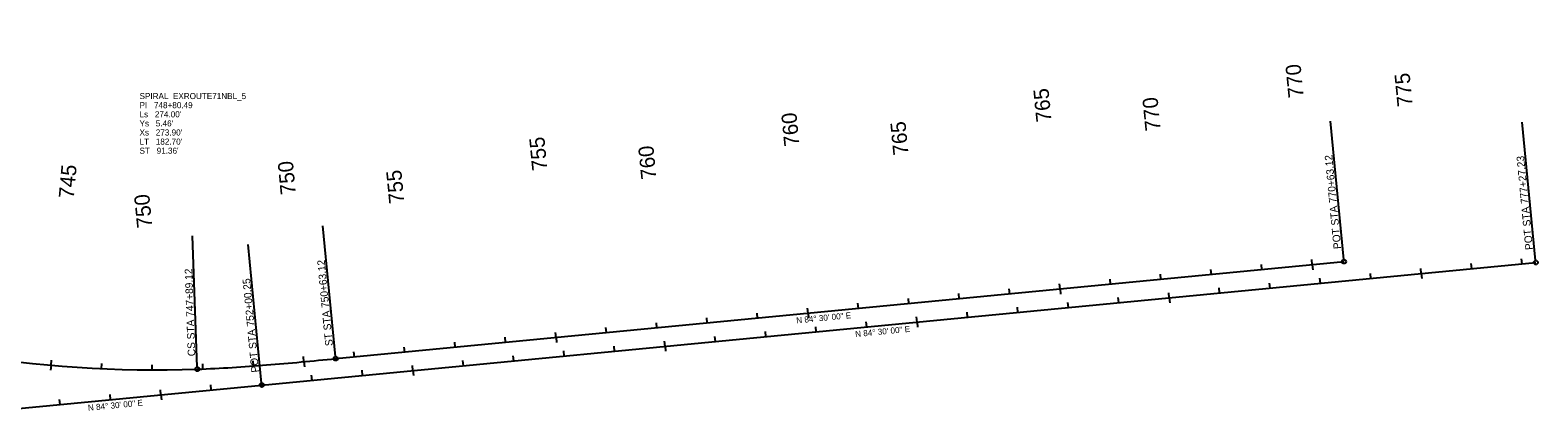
# Model space of a CAD drawing. Extents: x 2819977 to 2827606, y 116785 to 150320.
# Drawn here: x 2824629 to 2827606, y 145341 to 146093 of the extents above; entities that cross this region are included whole.
import ezdxf

# ---------------------------------------------------------------- set-up
doc = ezdxf.new("R2010")
doc.units = 0
for name, color, linetype in [('Default', 7, 'Continuous'), ('Modeling-Contours-Major-Existing', 7, 'Continuous'), ('Modeling-Contours-Minor-Existing', 7, 'Continuous'), ('Modeling-Triangle Verticies-Existing', 7, 'Continuous')]:
    doc.layers.add(name, color=color, linetype=linetype)

msp = doc.modelspace()

# ---------------------------------------------------------------- linework, layer by layer
at = {"layer": 'Default'}
msp.add_line((2825086.6, 145391.7), (2827601.9, 145633.9), dxfattribs=at)
msp.add_arc((2824876.4, 147713.4), 2291.8, 224.9911, 272.075, dxfattribs=at)
msp.add_open_spline([(2824959.3, 145423.1), (2824982.2, 145423.9), (2825027.8, 145426.2), (2825096.1, 145431.3), (2825164.3, 145437.2), (2825209.8, 145441.7), (2825232.5, 145443.9)], degree=3, dxfattribs=at)
at = {"layer": 'Modeling-Contours-Major-Existing'}
for p, q in [((2825086.6, 145391.7), (2827601.9, 145633.9)), ((2825232.5, 145443.9), (2827223.3, 145635.6)), ((2827060.9, 145619.9), (2827060, 145629.9)), ((2827160.5, 145629.5), (2827159.5, 145639.5)), ((2827160.5, 145629.5), (2827161.4, 145619.6)), ((2827475.3, 145621.7), (2827474.3, 145631.6)), ((2827574.8, 145631.2), (2827573.9, 145641.2)), ((2826762.3, 145591.2), (2826761.3, 145601.1)), ((2826861.8, 145600.8), (2826860.9, 145610.7)), ((2826961.4, 145610.3), (2826960.4, 145620.3)), ((2827176.7, 145592.9), (2827175.7, 145602.9)), ((2827276.2, 145602.5), (2827275.3, 145612.4)), ((2827375.8, 145612.1), (2827374.8, 145622)), ((2827375.8, 145612.1), (2827376.7, 145602.1)), ((2826463.7, 145562.4), (2826462.7, 145572.4)), ((2826563.2, 145572), (2826562.3, 145582)), ((2826662.8, 145581.6), (2826661.8, 145591.5)), ((2826662.8, 145581.6), (2826663.7, 145571.6)), ((2826878.1, 145564.1), (2826877.1, 145574.1)), ((2826977.6, 145573.7), (2826976.6, 145583.7)), ((2827077.1, 145583.3), (2827076.2, 145593.3)), ((2826165.1, 145533.7), (2826164.1, 145543.6)), ((2826264.6, 145543.3), (2826263.6, 145553.2)), ((2826364.1, 145552.8), (2826363.2, 145562.8)), ((2826579.4, 145535.4), (2826578.5, 145545.4)), ((2826679, 145545), (2826678, 145554.9)), ((2826778.5, 145554.6), (2826777.6, 145564.5)), ((2826878.1, 145564.1), (2826879, 145554.2)), ((2825866.4, 145504.9), (2825865.5, 145514.9)), ((2825966, 145514.5), (2825965, 145524.5)), ((2826065.5, 145524.1), (2826064.6, 145534)), ((2826165.1, 145533.7), (2826166, 145523.7)), ((2826181.3, 145497.1), (2826180.3, 145507)), ((2826280.8, 145506.6), (2826279.9, 145516.6)), ((2826380.4, 145516.2), (2826379.4, 145526.2)), ((2826380.4, 145516.2), (2826381.3, 145506.3)), ((2826479.9, 145525.8), (2826478.9, 145535.8)), ((2825567.8, 145476.2), (2825566.9, 145486.1)), ((2825667.4, 145485.7), (2825666.4, 145495.7)), ((2825667.4, 145485.7), (2825668.3, 145475.8)), ((2825766.9, 145495.3), (2825765.9, 145505.3)), ((2825882.7, 145468.3), (2825881.7, 145478.3)), ((2825982.2, 145477.9), (2825981.2, 145487.8)), ((2826081.7, 145487.5), (2826080.8, 145497.4)), ((2825169.7, 145437.9), (2825168.7, 145447.9)), ((2825269.2, 145447.4), (2825268.2, 145457.4)), ((2825368.7, 145457), (2825367.8, 145466.9)), ((2825468.3, 145466.6), (2825467.3, 145476.5)), ((2825584, 145439.6), (2825583.1, 145449.5)), ((2825683.6, 145449.1), (2825682.6, 145459.1)), ((2825783.1, 145458.7), (2825782.2, 145468.7)), ((2825882.7, 145468.3), (2825883.6, 145458.4)), ((2824670.5, 145430.8), (2824669.6, 145420.9)), ((2824670.5, 145430.8), (2824671.4, 145440.8)), ((2824770.3, 145424), (2824770.7, 145434)), ((2824870.2, 145421.6), (2824870.3, 145431.6)), ((2824970.2, 145423.5), (2824969.8, 145433.5)), ((2825070, 145429.4), (2825069.3, 145439.4)), ((2825169.7, 145437.9), (2825170.6, 145427.9)), ((2825285.4, 145410.8), (2825284.5, 145420.8)), ((2825385, 145420.4), (2825384, 145430.3)), ((2825385, 145420.4), (2825385.9, 145410.4)), ((2825484.5, 145430), (2825483.5, 145439.9)), ((2824572.2, 145342.1), (2825086.6, 145391.7)), ((2824986.8, 145382), (2824985.8, 145392)), ((2825086.3, 145391.6), (2825085.4, 145401.6)), ((2825185.9, 145401.2), (2825184.9, 145411.2)), ((2824688.2, 145353.3), (2824687.2, 145363.2)), ((2824787.7, 145362.9), (2824786.8, 145372.8)), ((2824887.3, 145372.5), (2824886.3, 145382.4)), ((2824887.3, 145372.5), (2824888.2, 145362.5))]:
    msp.add_line(p, q, dxfattribs=at)
msp.add_arc((2824876.4, 147713.4), 2291.8, 224.9911, 272.075, dxfattribs=at)
msp.add_open_spline([(2824959.3, 145423.1), (2824982.2, 145423.9), (2825027.8, 145426.2), (2825096.1, 145431.3), (2825164.3, 145437.2), (2825209.8, 145441.7), (2825232.5, 145443.9)], degree=3, dxfattribs=at)
at = {"layer": 'Modeling-Contours-Minor-Existing'}
for p, q in [((2827222.9, 145639.6), (2827196.6, 145913)), ((2827601.6, 145637.8), (2827575.2, 145911.3)), ((2824959.2, 145427.1), (2824949.8, 145686.6)), ((2825232.1, 145447.9), (2825207.2, 145706.4)), ((2825086.2, 145395.6), (2825059.9, 145669.2))]:
    msp.add_line(p, q, dxfattribs=at)
for centre in [(2827223.3, 145635.6), (2827601.9, 145633.9), (2825232.5, 145443.9), (2824959.3, 145423.1), (2825086.6, 145391.7)]:
    msp.add_circle(centre, 4, dxfattribs=at)

# ---------------------------------------------------------------- texts
at = {"layer": 'Modeling-Contours-Major-Existing'}
for s, rotation, p in [(' 770', 95.5, (2827144.7, 145949.5)), (' 775', 95.5, (2827360, 145932)), (' 765', 95.5, (2826647, 145901.6)), (' 770', 95.5, (2826862.3, 145884.1)), (' 760', 95.5, (2826149.3, 145853.6)), (' 765', 95.5, (2826364.6, 145836.2)), (' 755', 95.5, (2825651.6, 145805.7)), (' 760', 95.5, (2825866.9, 145788.3)), (' 745', 84.8469, (2824714.2, 145748.2)), (' 750', 95.3182, (2825154.9, 145757.9)), (' 755', 95.5, (2825369.2, 145740.3)), (' 750', 95.5, (2824871.5, 145692.4))]:
    msp.add_text(s, height=30, rotation=rotation, dxfattribs=at).set_placement(p)
at = {"layer": 'Modeling-Contours-Minor-Existing'}
for s, height, rotation, p in [('POT STA 770+63.12', 15, 95.5, (2827217.8, 145661.2)), ('POT STA 777+27.23', 15, 95.5, (2827596.5, 145659.4)), ('ST STA 750+63.12', 15, 95.5, (2825227, 145469.5)), ('CS STA 747+89.12', 15, 92.075, (2824955.4, 145448.9)), ('POT STA 752+00.25', 15, 95.5, (2825081.1, 145417.2)), ('N 84%%d 30\' 00" E', 12, 5.5, (2826142.3, 145513.4)), ('N 84%%d 30\' 00" E', 12, 5.5, (2826258.6, 145486.4)), ('N 84%%d 30\' 00" E', 12, 5.5, (2824743.8, 145340.6))]:
    msp.add_text(s, height=height, rotation=rotation, dxfattribs=at).set_placement(p)
at = {"layer": 'Modeling-Triangle Verticies-Existing'}
for s, p in [('SPIRAL  EXROUTE71NBL_5', (2824845.1, 145956.8)), ('PI   748+80.49', (2824845.1, 145938.8)), ("Ls   274.00'", (2824845.1, 145920.8)), ("Ys   5.46'", (2824845.1, 145902.8)), ("Xs   273.90'", (2824845.1, 145884.8)), ("LT   182.70'", (2824845.1, 145866.8)), ("ST   91.36'", (2824845.1, 145848.8))]:
    msp.add_text(s, height=12, dxfattribs=at).set_placement(p)

doc.saveas('drawing.dxf')
